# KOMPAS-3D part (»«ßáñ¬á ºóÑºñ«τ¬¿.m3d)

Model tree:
1. Эскиз:1
2. Операция выдавливания:1
     Расстояние 1 = 1
3. Эскиз:2
4. Вырезать элемент выдавливания:1
     Расстояние 1 = 0.5; Угол 1 = 8
5. Массив по концентрической сетке:1  (with: Вырезать элемент выдавливания:1)  (labels: Экземпляр ( 1, 1 ); Экземпляр ( 1, 2 ); Экземпляр ( 1, 3 ); Экземпляр ( 1, 4 ))
     N 2 = 16; Шаг 2 = 360; Номер 2 = 1
6. Эскиз:3
7. Отверстие:1

Referenced files in C:\Program Files\ASCON\KOMPAS-3D V13 Home\Sys\: holelib.lfr
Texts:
  Сплав АЛ8  ГОСТ 1583-93
  Отверстие 01
  (вариант 1)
